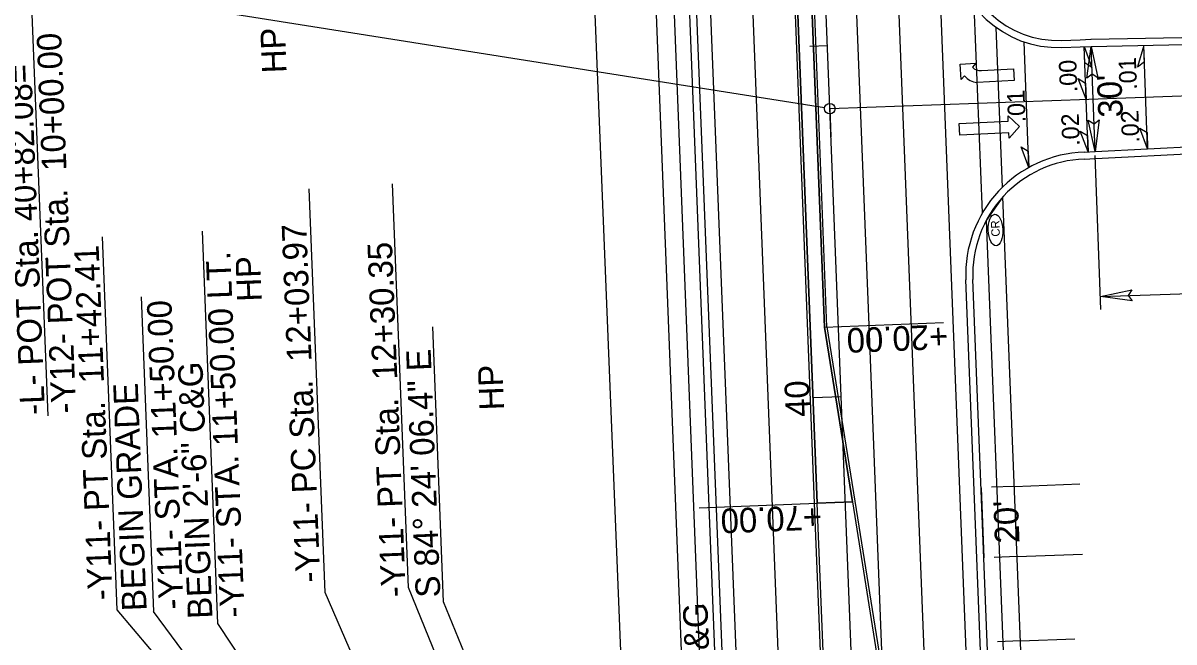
# Model space of a CAD drawing. Extents: x 1627861 to 1629601, y 761281 to 766239.
# Drawn here: x 1628159.8 to 1628487.4, y 764403.8 to 764580 of the extents above; entities that cross this region are included whole.
import ezdxf

# ---------------------------------------------------------------- set-up
doc = ezdxf.new("R2010")
doc.units = 0
for name, color, linetype in [('Cogo Default Point CELL', 7, 'Continuous'), ('Exist Other Culture Sign Leader', 7, 'Continuous'), ('Exist Property Tie Line Leader', 7, 'Continuous'), ('Exist Property Tie Line Text', 7, 'Continuous'), ('Exist Right of Way Line Leader', 7, 'Continuous'), ('Exist Right of Way Monument Leader', 7, 'Continuous'), ('Exist Right of Way Monument Text', 7, 'Continuous'), ('Exist Utilities Gas Meter CELL', 7, 'Continuous'), ('Exist Utilities Gas Meter Cogo Elevation', 7, 'Continuous'), ('Exist Utilities Gas Meter Cogo Number', 7, 'Continuous'), ('Exist Utilities Gas UG Line', 7, 'Continuous'), ('Exist Utilities Other Unknown UG SUE Text', 7, 'Continuous'), ('Exist Utilities Power UG Cable SUE LOS B Cogo Point CELL', 7, 'Continuous'), ('Exist Utilities Telephone UG Cable SUE LOS B Cogo Comment', 7, 'Continuous'), ('Exist Utilities Telephone UG Cable SUE LOS B Cogo Point CELL', 7, 'Continuous'), ('Exist Utilities Water Fire Hydrant Cogo Elevation', 7, 'Continuous'), ('Exist Utilities Water Fire Hydrant Cogo Number', 7, 'Continuous'), ('Exist Utilities Water Meter Cogo Elevation', 7, 'Continuous'), ('Exist Utilities Water UG Line SUE LOS B Cogo Number', 7, 'Continuous'), ('Exist Utilities Water Valve CELL', 7, 'Continuous'), ('Matchline', 7, 'Continuous'), ('Scratch_Level_0', 7, 'Continuous'), ('Scratch_Level_1', 7, 'Continuous'), ('Typical Terminator CELL', 7, 'Continuous')]:
    doc.layers.add(name, color=color, linetype=linetype)

msp = doc.modelspace()

# ---------------------------------------------------------------- linework, layer by layer
at = {"layer": 'Exist Property Tie Line Text'}
msp.add_line((1628388.77, 764573.52), (1628383.77, 764573.33), dxfattribs=at)
at = {"layer": 'Exist Right of Way Line Leader'}
for p, q in [((1628166.92, 764468.18), (1628162.05, 764591.66)), ((1628387.99, 764555.85), (1628162.05, 764591.66)), ((1628245.8, 764417.86), (1628241.27, 764532.77)), ((1628269.51, 764419.31), (1628264.98, 764534.22)), ((1628186.59, 764412.91), (1628182.4, 764519.14)), ((1628279.53, 764415.15), (1628276.45, 764493.46)), ((1628292.11, 764311.82), (1628245.8, 764417.86)), ((1628317.11, 764302.8), (1628269.51, 764419.31)), ((1628326.41, 764300.41), (1628279.53, 764415.15)), ((1628241.92, 764347.65), (1628186.59, 764412.91))]:
    msp.add_line(p, q, dxfattribs=at)
msp.add_circle((1628389.47, 764555.61), 1.5, dxfattribs=at)
at = {"layer": 'Exist Right of Way Monument Leader'}
for p, q in [((1628426.57, 764568.27), (1628431.06, 764568.56)), ((1628426.86, 764563.88), (1628426.57, 764568.27)), ((1628431.06, 764568.56), (1628430.07, 764567.46)), ((1628427.85, 764564.99), (1628426.86, 764563.88)), ((1628432.63, 764566.44), (1628441.77, 764566.93)), ((1628441.77, 764566.93), (1628441.94, 764563.64)), ((1628441.94, 764563.64), (1628431.41, 764563.07)), ((1628426.3, 764551.36), (1628440.28, 764552.02)), ((1628426.45, 764548.07), (1628426.3, 764551.36)), ((1628440.28, 764552.02), (1628440.21, 764553.52)), ((1628440.21, 764553.52), (1628443.51, 764550.57)), ((1628440.44, 764548.72), (1628426.45, 764548.07)), ((1628440.51, 764547.23), (1628440.44, 764548.72)), ((1628443.51, 764550.57), (1628440.51, 764547.23))]:
    msp.add_line(p, q, dxfattribs=at)
for centre, radius, start, end in [((1628432.44, 764569.7), 3.28, 223.403, 273.0612), ((1628431.92, 764568.28), 5.25, 219.0734, 264.3851)]:
    msp.add_arc(centre, radius, start, end, dxfattribs=at)
at = {"layer": 'Exist Right of Way Monument Text'}
for p, q in [((1628360.72, 764352.1), (1628349.87, 764627.31)), ((1628463.87, 764573.35), (1628563.87, 764575.2)), ((1628455.5, 764573.04), (1628460.77, 764573.23)), ((1628460.77, 764573.23), (1628463.87, 764573.35)), ((1628464.97, 764543.37), (1628564.84, 764548.72)), ((1628461.87, 764543.25), (1628464.97, 764543.37)), ((1628451.66, 763911.37), (1628428.17, 764506.9)), ((1628442, 764448.05), (1628460.66, 764448.78)), ((1628418.64, 763593.94), (1628385.15, 764443.28)), ((1628396.63, 764443.82), (1628404.6, 764394.05)), ((1628442.79, 764428.06), (1628461.45, 764428.8)), ((1628443.74, 764404.07), (1628459.2, 764404.68))]:
    msp.add_line(p, q, dxfattribs=at)
for centre, radius, start, end in [((1628454.41, 764603.02), 30, 182.2582, 272.0964), ((1628463.15, 764508.28), 35, 92.0964, 182.2582)]:
    msp.add_arc(centre, radius, start, end, dxfattribs=at)
at = {"layer": 'Exist Utilities Gas Meter CELL'}
for p, q in [((1628486.22, 762102.11), (1628373.12, 764970.45)), ((1628389.47, 764555.61), (1628586.15, 764562.81)), ((1628389.47, 764555.61), (1628586.15, 764562.81))]:
    msp.add_line(p, q, dxfattribs=at)
at = {"layer": 'Exist Utilities Gas Meter Cogo Elevation'}
for p, q in [((1628358.72, 764352.02), (1628347.87, 764627.23)), ((1628455.43, 764575.04), (1628460.7, 764575.23)), ((1628453.66, 763911.45), (1628430.17, 764506.97))]:
    msp.add_line(p, q, dxfattribs=at)
for centre, radius, start, end in [((1628454.41, 764603.02), 28, 182.2582, 272.0964), ((1628463.15, 764508.28), 33, 92.0964, 182.2582)]:
    msp.add_arc(centre, radius, start, end, dxfattribs=at)
at = {"layer": 'Exist Utilities Gas Meter Cogo Number'}
for points in [[(1628462.65, 764564.3), (1628463.87, 764573.35), (1628465.8, 764564.36), (1628464.16, 764565.45)], [(1628466.19, 764552.42), (1628464.97, 764543.37), (1628463.04, 764552.35), (1628464.68, 764551.26)], [(1628475.53, 764500.86), (1628466.48, 764502.08), (1628475.47, 764504.01), (1628474.38, 764502.37)]]:
    msp.add_lwpolyline(points, close=True, dxfattribs=at)
at = {"layer": 'Exist Utilities Gas UG Line'}
for p, q in [((1628400.66, 764493.93), (1628388.84, 764793.7)), ((1628462.18, 763238.38), (1628400.83, 764794.17)), ((1628474.17, 763238.85), (1628412.82, 764794.64)), ((1628408.48, 763242.45), (1628347.37, 764792.06)), ((1628420.44, 763243.74), (1628359.36, 764792.53)), ((1628385.15, 764443.28), (1628371.43, 764791.01)), ((1628388.67, 764493.5), (1628376.93, 764791.23)), ((1628388.67, 764493.5), (1628396.63, 764443.82)), ((1628404.6, 764394.05), (1628400.66, 764493.93))]:
    msp.add_line(p, q, dxfattribs=at)
at = {"layer": 'Exist Utilities Other Unknown UG SUE Text'}
for p, q in [((1628385.9, 764443.31), (1628372.18, 764791.04)), ((1628372.18, 764791.04), (1628385.9, 764443.31)), ((1628376.18, 764791.2), (1628387.92, 764493.43)), ((1628387.92, 764493.43), (1628376.18, 764791.2)), ((1628387.92, 764493.43), (1628395.89, 764443.7)), ((1628395.89, 764443.7), (1628387.92, 764493.43)), ((1628395.89, 764443.7), (1628385.9, 764443.31)), ((1628385.9, 764443.31), (1628395.89, 764443.7))]:
    msp.add_line(p, q, dxfattribs=at)
at = {"layer": 'Exist Utilities Telephone UG Cable SUE LOS B Cogo Comment'}
for p, q in [((1628432.93, 764525.93), (1628430.61, 764584.76)), ((1628438.64, 764533.27), (1628436.85, 764578.69))]:
    msp.add_line(p, q, dxfattribs=at)
at = {"layer": 'Exist Utilities Telephone UG Cable SUE LOS B Cogo Point CELL'}
for p, q in [((1628463.84, 764575.35), (1628563.84, 764577.2)), ((1628460.7, 764575.23), (1628463.8, 764575.35)), ((1628465.08, 764541.37), (1628564.95, 764546.72)), ((1628461.94, 764541.26), (1628465.05, 764541.37))]:
    msp.add_line(p, q, dxfattribs=at)
at = {"layer": 'Exist Utilities Water Fire Hydrant Cogo Elevation'}
msp.add_ellipse((1628436.63, 764521.05), major_axis=(-0.18, 4.48), ratio=0.462467, dxfattribs=at)
at = {"layer": 'Exist Utilities Water Fire Hydrant Cogo Number'}
msp.add_line((1628333.03, 764325.09), (1628320.13, 764646.7), dxfattribs=at)
at = {"layer": 'Exist Utilities Water Meter Cogo Elevation'}
for p, q in [((1628389.47, 764555.61), (1628389.77, 764547.62)), ((1628392.71, 764473.6), (1628384.71, 764473.28))]:
    msp.add_line(p, q, dxfattribs=at)
at = {"layer": 'Exist Utilities Water UG Line SUE LOS B Cogo Number'}
for p, q in [((1628446.12, 764538.86), (1628444.82, 764574.59)), ((1628462.97, 764543.29), (1628461.88, 764573.27)), ((1628479.95, 764544.17), (1628478.87, 764573.63))]:
    msp.add_line(p, q, dxfattribs=at)
at = {"layer": 'Exist Utilities Water Valve CELL'}
for p, q in [((1628350.14, 764328.49), (1628337.55, 764647.86)), ((1628342.77, 764642.27), (1628354.88, 764335.22)), ((1628438.75, 764530.5), (1628434.01, 764523.77)), ((1628463.98, 763890.82), (1628438.75, 764530.5)), ((1628434.01, 764523.77), (1628458.75, 763896.41))]:
    msp.add_line(p, q, dxfattribs=at)
at = {"layer": 'Matchline'}
for p, q in [((1628419.39, 763593.97), (1628385.9, 764443.31)), ((1628395.89, 764443.7), (1628403.85, 764393.98))]:
    msp.add_line(p, q, dxfattribs=at)
at = {"layer": 'Scratch_Level_0'}
for p, q in [((1628464.97, 764543.37), (1628463.87, 764573.35)), ((1628466.62, 764498.38), (1628465.01, 764542.23)), ((1628215.27, 764409.02), (1628210.87, 764520.7)), ((1628466.48, 764502.08), (1628566.42, 764505.74)), ((1628193.4, 764502), (1628196.93, 764412.48)), ((1628387.92, 764493.43), (1628421.79, 764494.76)), ((1628432.51, 764447.67), (1628433.3, 764427.68)), ((1628352.29, 764441.98), (1628385.9, 764443.31)), ((1628249.11, 764342.12), (1628196.93, 764412.48)), ((1628254.71, 764349.88), (1628215.27, 764409.02))]:
    msp.add_line(p, q, dxfattribs=at)
at = {"layer": 'Scratch_Level_1'}
for p, q in [((1628442, 764448.05), (1628435.51, 764447.79)), ((1628442.79, 764428.06), (1628436.3, 764427.8)), ((1628443.74, 764404.07), (1628437.24, 764403.82))]:
    msp.add_line(p, q, dxfattribs=at)
at = {"layer": 'Typical Terminator CELL'}
for points in [[(1628461.88, 764573.27), (1628464.09, 764567.35), (1628462.05, 764568.65)], [(1628478.87, 764573.63), (1628477.1, 764567.56), (1628479.04, 764569)], [(1628462.42, 764558.28), (1628460.21, 764564.21), (1628462.26, 764562.91)], [(1628462.97, 764543.29), (1628460.76, 764549.22), (1628462.8, 764547.92)], [(1628479.95, 764544.17), (1628477.73, 764550.09), (1628479.78, 764548.79)], [(1628446.12, 764538.86), (1628443.91, 764544.78), (1628445.96, 764543.48)]]:
    msp.add_lwpolyline(points, close=True, dxfattribs=at)

# ---------------------------------------------------------------- texts
at = {"layer": 'Cogo Default Point CELL'}
msp.add_text('S 84%%d 24\' 06.4" E', height=7, rotation=92.2582, dxfattribs=at).set_placement((1628278.63, 764416.54))
at = {"layer": 'Exist Other Culture Sign Leader'}
for s, p in [('HP', (1628234.85, 764565.83)), ('HP', (1628227.79, 764500.78)), ('-Y11- STA. 11+50.00', (1628205.51, 764413.09)), ('HP', (1628296.78, 764469.84)), ('BEGIN GRADE', (1628195.02, 764412.68))]:
    msp.add_text(s, height=7, rotation=92.2582, dxfattribs=at).set_placement(p)
at = {"layer": 'Exist Property Tie Line Leader'}
msp.add_text('40', height=7, rotation=92.2582, dxfattribs=at).set_placement((1628383.92, 764467.96))
at = {"layer": 'Exist Right of Way Line Leader'}
for s, p in [('-Y12- POT Sta.  10+00.00', (1628174.93, 764468.92)), ('-L- POT Sta. 40+82.08=', (1628166.06, 764468.57)), ('-Y11- PC Sta.  12+03.97', (1628244.45, 764420.79)), ('-Y11- PT Sta.  11+42.41', (1628185.31, 764415.74)), ('-Y11- PT Sta.  12+30.35', (1628268.81, 764416.65))]:
    msp.add_text(s, height=7, rotation=92.2582, dxfattribs=at).set_placement(p)
at = {"layer": 'Exist Utilities Power UG Cable SUE LOS B Cogo Point CELL'}
for s, rotation, p in [("30'", 92.0586, (1628472.91, 764553.22)), ('-Y11- STA. 11+50.00 LT.', 92.2582, (1628222.91, 764410.85)), ('BEGIN 2\'-6" C&G', 92.2582, (1628213.74, 764410.48))]:
    msp.add_text(s, height=7, rotation=rotation, dxfattribs=at).set_placement(p)
at = {"layer": 'Exist Utilities Water Fire Hydrant Cogo Elevation'}
msp.add_text('CR', height=2.4, rotation=92.2582, dxfattribs=at).set_placement((1628437.89, 764519.21))
at = {"layer": 'Exist Utilities Water UG Line SUE LOS B Cogo Number'}
for s, p in [('.00', (1628459.97, 764560.33)), ('.01', (1628476.94, 764561.03)), ('.01', (1628445.22, 764551.75)), ('.02', (1628477.64, 764545.96)), ('.02', (1628460.66, 764545.08))]:
    msp.add_text(s, height=5, rotation=92.0964, dxfattribs=at).set_placement(p)
at = {"layer": 'Scratch_Level_0'}
for s, rotation, p in [('+20.00', 182.2582, (1628423.01, 764494.21)), ("20'", 92.2582, (1628443.5, 764431.96)), ('+70.00', 182.2582, (1628387.12, 764442.8)), ('2\'-6" C&G', 92.0586, (1628356.1, 764373.59))]:
    msp.add_text(s, height=7, rotation=rotation, dxfattribs=at).set_placement(p)

doc.saveas('drawing.dxf')
